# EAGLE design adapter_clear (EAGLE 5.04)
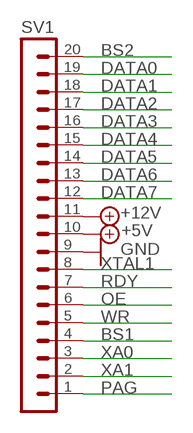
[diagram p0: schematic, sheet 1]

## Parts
SV1  MA20-1  [MA20-1]

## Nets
+5V: SV1.10
+12V: SV1.11
BS1: SV1.4
BS2: SV1.20
DATA0: SV1.19
DATA1: SV1.18
DATA2: SV1.17
DATA3: SV1.16
DATA4: SV1.15
DATA5: SV1.14
DATA6: SV1.13
DATA7: SV1.12
GND: SV1.9
OE: SV1.6
PAG: SV1.1
RDY: SV1.7
WR: SV1.5
XA0: SV1.3
XA1: SV1.2
XTAL1: SV1.8

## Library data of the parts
SV1 = con-lstb:MA20-1: PIN HEADER

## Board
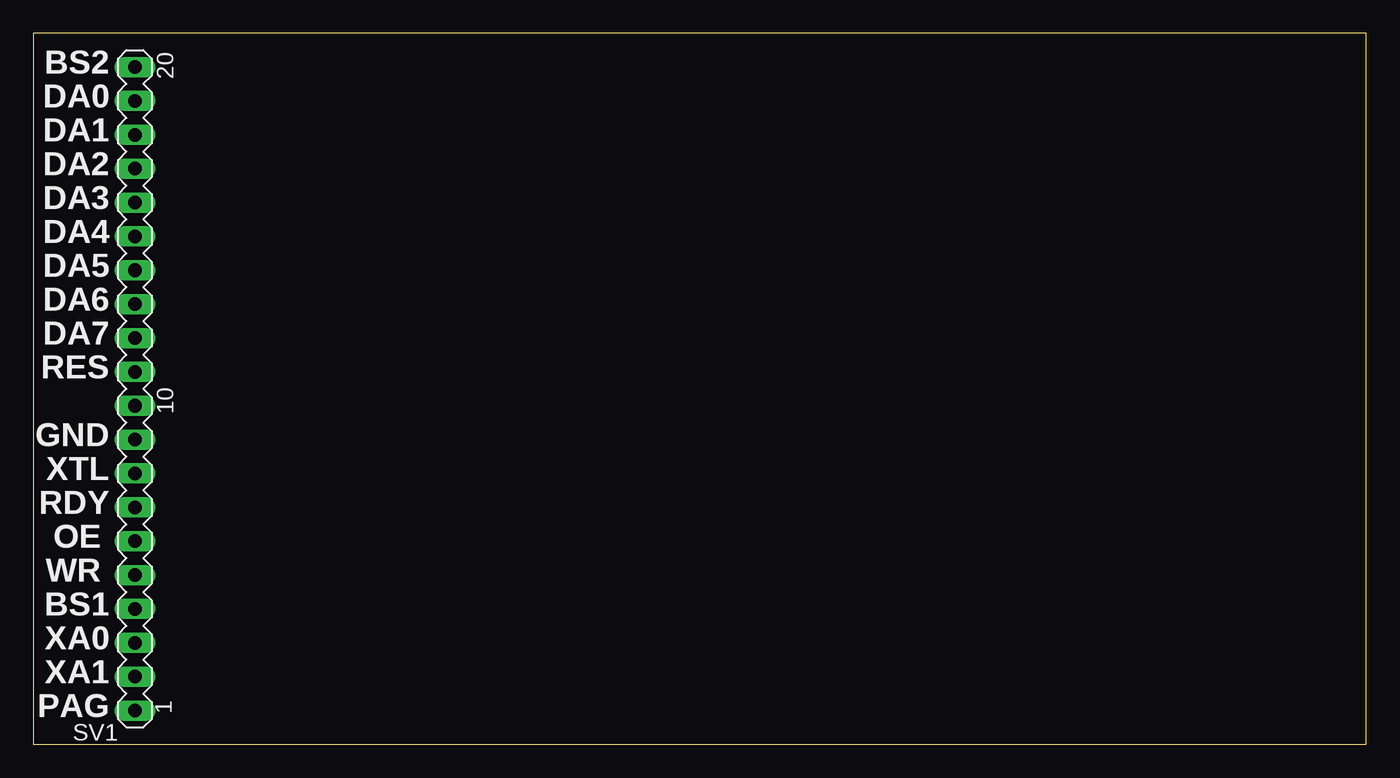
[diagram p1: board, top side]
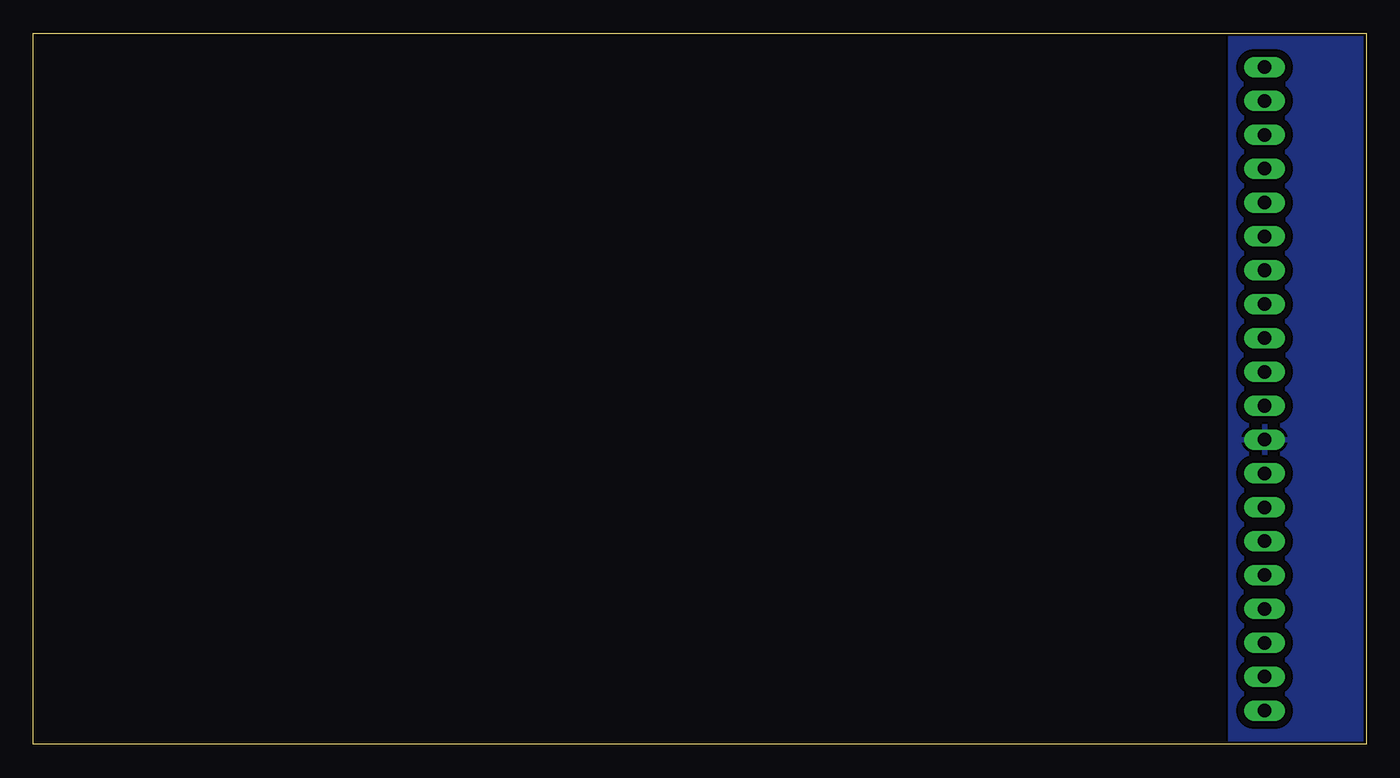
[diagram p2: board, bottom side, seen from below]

Size 100 x 53.33 mm. Coordinates in mm from the lower left corner, seen from the top.
Outline: 0,0 100,0 100,53.33 0,53.33 0,0
Copper layers (1*16): Top 0.035mm / dielectric 1.5mm / Bottom 0.035mm
Design rules "default *": minimum track width 10mil, minimum drill 24mil, track to track 24mil, track to pad 24mil, pad to pad 8mil, via to via 8mil, smd to smd 8mil, copper to edge 8mil, drill to drill 8mil, minimum pad ring 10mil, minimum via ring 8mil, stop-mask expansion 4mil, vias tented up to drill 0mil, thermal gap 10mil

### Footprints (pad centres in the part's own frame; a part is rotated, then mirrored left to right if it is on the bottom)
MA20-1 = drill 1.016 long: 1 -24.13,0; 2 -21.59,0; 3 -19.05,0; 4 -16.51,0; 5 -13.97,0; 6 -11.43,0; 7 -8.89,0; 8 -6.35,0; 9 -3.81,0; 10 -1.27,0; 11 1.27,0; 12 3.81,0; 13 6.35,0; 14 8.89,0; 15 11.43,0; 16 13.97,0; 17 16.51,0; 18 19.05,0; 19 21.59,0; 20 24.13,0

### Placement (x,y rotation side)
SV1  7.62,26.67 90 top

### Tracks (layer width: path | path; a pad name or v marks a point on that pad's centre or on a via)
GND
  pour Bottom: 0,53.34 10.16,53.34 10.16,0 0,0

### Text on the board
tPlace: BS2 | DA0 | DA1 | DA2 | DA3 | DA4 | DA5 | DA6 | DA7 | RES | GND | XTL | RDY | OE | WR | BS1 | XA0 | XA1 | PAG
